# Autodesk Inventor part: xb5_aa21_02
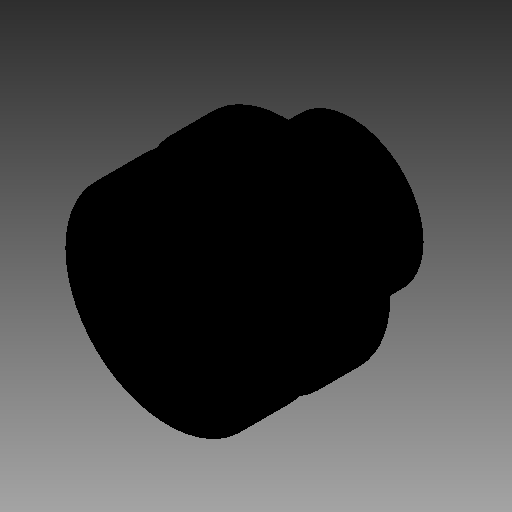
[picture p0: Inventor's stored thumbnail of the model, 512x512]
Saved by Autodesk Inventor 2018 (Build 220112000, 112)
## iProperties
Company: TraceParts S.A.
Created: 2018-05
Part Number: xb5_aa21_02
Checked By: TraceParts S.A.
Material: Generic
Catalog Web Link: www.traceparts.com
Document SubType Name: Modeling
Designer: TraceParts
Density: 1 g/cm^3
Appearance: Default
Author: TraceParts
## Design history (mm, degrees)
feature "xb5_aa21_02.ipt"
body "Solid1"
